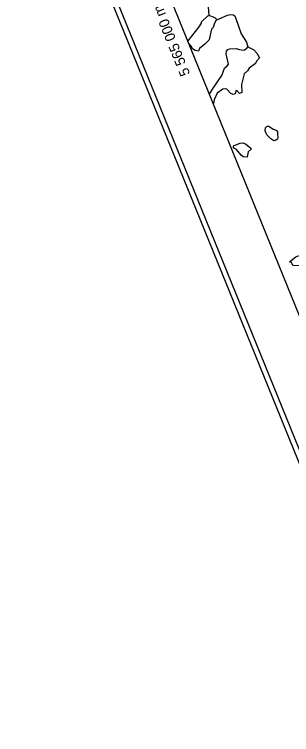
# Model space of a CAD drawing. Extents: x 362852 to 366875, y 5563573 to 5566479.
# Drawn here: x 362852.2 to 362961.3, y 5564714.4 to 5564998.2 of the extents above; entities that cross this region are included whole.
import ezdxf

# ---------------------------------------------------------------- set-up
doc = ezdxf.new("R2010")
doc.units = 0
for name, color, linetype in [('Niveau 4', 7, 'Continuous'), ('Niveau 60', 7, 'Continuous'), ('Niveau 61', 7, 'Continuous')]:
    doc.layers.add(name, color=color, linetype=linetype)

msp = doc.modelspace()

# ---------------------------------------------------------------- linework, layer by layer
at = {"layer": 'Niveau 4'}
for points in [[(362924.13, 5565010.01), (362926.34, 5565007.73), (362928.7, 5565004.82), (362928.84, 5565004.32), (362928.53, 5565001.17), (362928.76, 5564997.72)], [(362931.63, 5564995.88), (362936.13, 5564997.89), (362937.4, 5564998.17), (362938.25, 5564998.09), (362938.95, 5564997.63), (362939.39, 5564996.56), (362941.47, 5564990.57), (362943.56, 5564987.24), (362944.14, 5564985.42)], [(362920.57, 5564987.64), (362920.58, 5564987.79), (362924.87, 5564993.3), (362925.84, 5564994.71), (362925.91, 5564995.3), (362928.4, 5564997.6), (362928.76, 5564997.72)], [(362931.63, 5564995.88), (362930.98, 5564994.73), (362930.38, 5564993.03), (362929.77, 5564992.4), (362929.44, 5564990.63), (362928.82, 5564988.23), (362927.14, 5564986.52), (362925, 5564984.75), (362924.62, 5564983.71), (362923.29, 5564984.03), (362922.27, 5564984.67), (362921.91, 5564985.52), (362920.99, 5564986.61)], [(362928.76, 5564997.72), (362929.01, 5564997.8), (362930.39, 5564997.19), (362931.46, 5564996.75), (362931.63, 5564995.88)], [(362929.04, 5564966.77), (362930.23, 5564968.71), (362933.88, 5564974.08), (362934.85, 5564977), (362935.98, 5564977.91), (362936.41, 5564978.53), (362935.49, 5564982.67), (362935.66, 5564983.75), (362936.17, 5564984.34), (362936.87, 5564984.63), (362939.45, 5564984.77), (362940.82, 5564984.34), (362942.38, 5564984.05), (362942.76, 5564984.21), (362943.63, 5564984.83), (362944.14, 5564985.42), (362944.63, 5564985.21), (362946.43, 5564984.21), (362947.6, 5564982.94), (362948.15, 5564981.96), (362948.68, 5564981.04), (362947.43, 5564979.82), (362947.06, 5564978.91), (362944.54, 5564976.98), (362943.9, 5564975.96), (362942.68, 5564974.82), (362941.57, 5564970.58), (362941.68, 5564967.48), (362940.79, 5564967.05), (362939.8, 5564968.21), (362939.41, 5564968.1), (362939.1, 5564966.9), (362938.3, 5564966.7), (362937.39, 5564967.07), (362935.84, 5564968.68), (362935.15, 5564968.83), (362934.23, 5564968.76), (362932.02, 5564967.14), (362930.81, 5564964.49), (362930.52, 5564963.13)], [(362954.35, 5564948.37), (362953.11, 5564949.23), (362951.53, 5564950.77), (362950.9, 5564952.26), (362951.08, 5564953.47), (362951.75, 5564954.13), (362952.32, 5564954.11), (362954.06, 5564952.96), (362955.23, 5564952.57), (362955.7, 5564952.2), (362955.74, 5564950.9), (362955.88, 5564949.83), (362955.7, 5564949.06), (362955.1, 5564948.69), (362954.35, 5564948.37)], [(362938.64, 5564946.6), (362941.11, 5564947.45), (362942.13, 5564947.57), (362943.22, 5564947.21), (362945.29, 5564945.44), (362945.44, 5564945.06), (362944.16, 5564944.08), (362943.96, 5564942.75), (362943.84, 5564942), (362942.18, 5564942.06), (362941.45, 5564942.76), (362939.59, 5564944.93), (362938.79, 5564945.35), (362938.34, 5564945.98), (362938.64, 5564946.6)], [(362960.54, 5564900.72), (362962.91, 5564902.72), (362963.52, 5564902.91), (362965.26, 5564903.27), (362966.78, 5564903.22), (362968.87, 5564902.9), (362969.4, 5564902.68), (362969.02, 5564902.08), (362967.01, 5564899.54), (362966.48, 5564899.32), (362964.75, 5564899.1), (362961.74, 5564899.22), (362961.47, 5564899.86), (362961.2, 5564900.37), (362960.54, 5564900.72)]]:
    msp.add_lwpolyline(points, dxfattribs=at)
at = {"layer": 'Niveau 60'}
for points in [[(363470.95, 5563573.17), (366875.21, 5564954.96), (366256.48, 5566479.3), (362852.22, 5565097.5), (363470.95, 5563573.17)], [(363472.05, 5563575.77), (366872.61, 5564956.04), (366255.38, 5566476.69), (362854.83, 5565096.41), (363472.05, 5563575.77)], [(362880.89, 5565085.4), (365762.56, 5566255.07), (366364.73, 5564771.5), (366364.73, 5564771.5), (363483.08, 5563601.82), (362880.89, 5565085.4)]]:
    msp.add_lwpolyline(points, dxfattribs=at)

# ---------------------------------------------------------------- texts
at = {"layer": 'Niveau 61'}
msp.add_text('5 565 000 m N.', height=4, rotation=112.0921, dxfattribs=at).set_placement((362921.45, 5564974.82))

doc.saveas('drawing.dxf')
